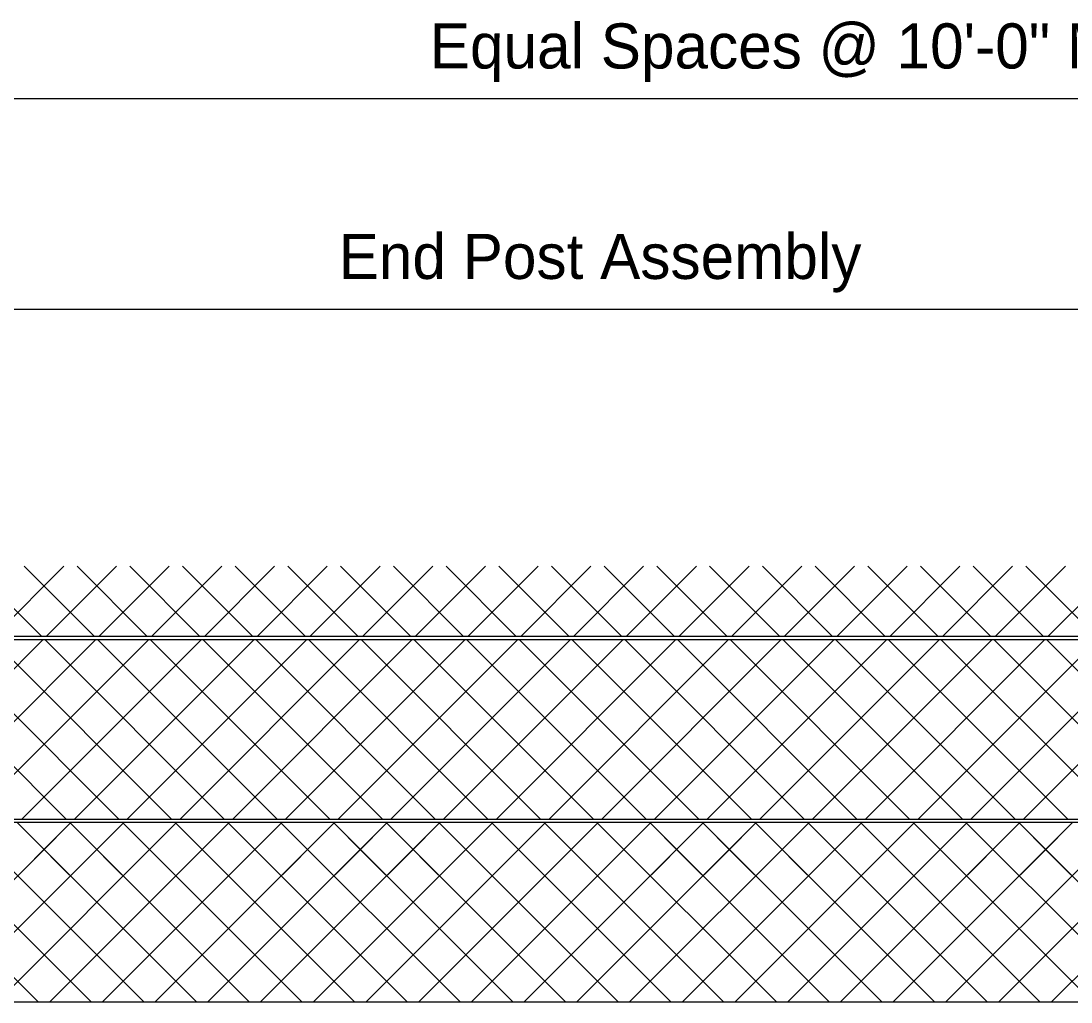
# Model space of a CAD drawing. Extents: x 0 to 41, y -96 to 25.
# Drawn here: x 7.464 to 12.158, y 20.57 to 24.956 of the extents above; entities that cross this region are included whole.
import ezdxf

# ---------------------------------------------------------------- set-up
doc = ezdxf.new("R2010")
doc.units = 0
for name, color, linetype in [('Dimension', 7, 'Continuous'), ('Miscellaneous', 7, 'Continuous'), ('SteelMisc', 7, 'Continuous'), ('TextStructures', 7, 'Continuous')]:
    doc.layers.add(name, color=color, linetype=linetype)

msp = doc.modelspace()

# ---------------------------------------------------------------- linework, layer by layer
at = {"layer": 'Dimension'}
for p, q in [((0.9439, 24.6092), (14.3237, 24.6092)), ((5.3237, 23.6682), (15.3237, 23.6682))]:
    msp.add_line(p, q, dxfattribs=at)
at = {"layer": 'Miscellaneous'}
for p, q in [((7.2428, 22.5181), (7.5553, 22.2055)), ((7.3422, 22.2055), (7.6547, 22.5181)), ((7.4785, 22.5181), (7.791, 22.2055)), ((7.5779, 22.2055), (7.8904, 22.5181)), ((7.7142, 22.5181), (8.0267, 22.2055)), ((7.8136, 22.2055), (8.1261, 22.5181)), ((7.9499, 22.5181), (8.2624, 22.2055)), ((8.0493, 22.2055), (8.3618, 22.5181)), ((8.1856, 22.5181), (8.4981, 22.2055)), ((8.285, 22.2055), (8.5975, 22.5181)), ((8.4213, 22.5181), (8.7338, 22.2055)), ((8.5207, 22.2055), (8.8332, 22.5181)), ((8.657, 22.5181), (8.9695, 22.2055)), ((8.7564, 22.2055), (9.0689, 22.5181)), ((8.8927, 22.5181), (9.2052, 22.2055)), ((8.9921, 22.2055), (9.3047, 22.5181)), ((9.1284, 22.5181), (9.4409, 22.2055)), ((9.2278, 22.2055), (9.5404, 22.5181)), ((9.3641, 22.5181), (9.6766, 22.2055)), ((9.4635, 22.2055), (9.7761, 22.5181)), ((9.5998, 22.5181), (9.9123, 22.2055)), ((9.6992, 22.2055), (10.0118, 22.5181)), ((9.8355, 22.5181), (10.148, 22.2055)), ((9.9349, 22.2055), (10.2475, 22.5181)), ((10.0712, 22.5181), (10.3837, 22.2055)), ((10.1706, 22.2055), (10.4832, 22.5181)), ((10.3069, 22.5181), (10.6194, 22.2055)), ((10.4063, 22.2055), (10.7189, 22.5181)), ((10.5426, 22.5181), (10.8551, 22.2055)), ((10.642, 22.2055), (10.9546, 22.5181)), ((10.7783, 22.5181), (11.0908, 22.2055)), ((10.8777, 22.2055), (11.1903, 22.5181)), ((11.014, 22.5181), (11.3265, 22.2055)), ((11.1134, 22.2055), (11.426, 22.5181)), ((11.2497, 22.5181), (11.5622, 22.2055)), ((11.3491, 22.2055), (11.6617, 22.5181)), ((11.4854, 22.5181), (11.7979, 22.2055)), ((11.5848, 22.2055), (11.8974, 22.5181)), ((11.7211, 22.5181), (12.0336, 22.2055)), ((11.8205, 22.2055), (12.1331, 22.5181)), ((11.9568, 22.5181), (12.2693, 22.2055)), ((12.0562, 22.2055), (12.3688, 22.5181)), ((6.7605, 21.3881), (7.5632, 22.1908)), ((6.8629, 22.1908), (7.6656, 21.3881)), ((6.9962, 21.3881), (7.7989, 22.1908)), ((7.0986, 22.1908), (7.9013, 21.3881)), ((7.2319, 21.3881), (8.0346, 22.1908)), ((7.3343, 22.1908), (8.137, 21.3881)), ((7.4676, 21.3881), (8.2703, 22.1908)), ((7.57, 22.1908), (8.3727, 21.3881)), ((7.7033, 21.3881), (8.506, 22.1908)), ((7.8058, 22.1908), (8.6084, 21.3881)), ((7.939, 21.3881), (8.7417, 22.1908)), ((8.0415, 22.1908), (8.8441, 21.3881)), ((8.1747, 21.3881), (8.9774, 22.1908)), ((8.2772, 22.1908), (9.0798, 21.3881)), ((8.4104, 21.3881), (9.2131, 22.1908)), ((8.5129, 22.1908), (9.3155, 21.3881)), ((8.6461, 21.3881), (9.4488, 22.1908)), ((8.7486, 22.1908), (9.5512, 21.3881)), ((8.8818, 21.3881), (9.6845, 22.1908)), ((8.9843, 22.1908), (9.7869, 21.3881)), ((9.1175, 21.3881), (9.9202, 22.1908)), ((9.22, 22.1908), (10.0226, 21.3881)), ((9.3532, 21.3881), (10.1559, 22.1908)), ((9.4557, 22.1908), (10.2583, 21.3881)), ((9.5889, 21.3881), (10.3916, 22.1908)), ((9.6914, 22.1908), (10.494, 21.3881)), ((9.8246, 21.3881), (10.6273, 22.1908)), ((9.9271, 22.1908), (10.7297, 21.3881)), ((10.0603, 21.3881), (10.863, 22.1908)), ((10.1628, 22.1908), (10.9654, 21.3881)), ((10.296, 21.3881), (11.0987, 22.1908)), ((10.3985, 22.1908), (11.2011, 21.3881)), ((10.5317, 21.3881), (11.3344, 22.1908)), ((10.6342, 22.1908), (11.4368, 21.3881)), ((10.7674, 21.3881), (11.5701, 22.1908)), ((10.8699, 22.1908), (11.6725, 21.3881)), ((11.0031, 21.3881), (11.8058, 22.1908)), ((11.1056, 22.1908), (11.9082, 21.3881)), ((11.2388, 21.3881), (12.0415, 22.1908)), ((11.3413, 22.1908), (12.1439, 21.3881)), ((11.4745, 21.3881), (12.2772, 22.1908)), ((11.577, 22.1908), (12.3796, 21.3881)), ((11.7103, 21.3881), (12.5129, 22.1908)), ((11.8127, 22.1908), (12.6153, 21.3881)), ((11.946, 21.3881), (12.7486, 22.1908)), ((12.0484, 22.1908), (12.851, 21.3881)), ((6.7375, 21.3734), (7.541, 20.57)), ((6.8851, 20.57), (7.6886, 21.3734)), ((6.9732, 21.3734), (7.7767, 20.57)), ((7.1208, 20.57), (7.9243, 21.3734)), ((7.2089, 21.3734), (8.0124, 20.57)), ((7.3565, 20.57), (8.16, 21.3734)), ((7.4446, 21.3734), (8.2481, 20.57)), ((7.5922, 20.57), (8.3957, 21.3734)), ((7.6803, 21.3734), (8.4838, 20.57)), ((7.8279, 20.57), (8.6314, 21.3734)), ((7.916, 21.3734), (8.7195, 20.57)), ((8.0636, 20.57), (8.8671, 21.3734)), ((8.1517, 21.3734), (8.9552, 20.57)), ((8.2993, 20.57), (9.1028, 21.3734)), ((8.3874, 21.3734), (9.1909, 20.57)), ((8.535, 20.57), (9.3385, 21.3734)), ((8.6231, 21.3734), (9.4266, 20.57)), ((8.7707, 20.57), (9.5742, 21.3734)), ((8.8589, 21.3734), (9.6623, 20.57)), ((9.0064, 20.57), (9.8099, 21.3734)), ((9.0946, 21.3734), (9.898, 20.57)), ((9.2422, 20.57), (10.0456, 21.3734)), ((9.3303, 21.3734), (10.1337, 20.57)), ((9.4779, 20.57), (10.2813, 21.3734)), ((9.566, 21.3734), (10.3694, 20.57)), ((9.7136, 20.57), (10.517, 21.3734)), ((9.8017, 21.3734), (10.6051, 20.57)), ((9.9493, 20.57), (10.7527, 21.3734)), ((10.0374, 21.3734), (10.8408, 20.57)), ((10.185, 20.57), (10.9884, 21.3734)), ((10.2731, 21.3734), (11.0765, 20.57)), ((10.4207, 20.57), (11.2241, 21.3734)), ((10.5088, 21.3734), (11.3122, 20.57)), ((10.6564, 20.57), (11.4598, 21.3734)), ((10.7445, 21.3734), (11.5479, 20.57)), ((10.8921, 20.57), (11.6955, 21.3734)), ((10.9802, 21.3734), (11.7836, 20.57)), ((11.1278, 20.57), (11.9312, 21.3734)), ((11.2159, 21.3734), (12.0193, 20.57)), ((11.3635, 20.57), (12.1669, 21.3734)), ((11.4516, 21.3734), (12.255, 20.57)), ((11.5992, 20.57), (12.4026, 21.3734)), ((11.6873, 21.3734), (12.4907, 20.57)), ((11.8349, 20.57), (12.6383, 21.3734)), ((11.923, 21.3734), (12.7264, 20.57)), ((12.0706, 20.57), (12.874, 21.3734)), ((7.4537, 21.1385), (7.6203, 21.3051)), ((7.5129, 21.3051), (7.6795, 21.1385)), ((7.6894, 21.1385), (7.856, 21.3051)), ((7.7486, 21.3051), (7.9152, 21.1385)), ((7.9251, 21.1385), (8.0917, 21.3051)), ((7.9843, 21.3051), (8.1509, 21.1385)), ((8.1608, 21.1385), (8.3274, 21.3051)), ((8.22, 21.3051), (8.3867, 21.1385)), ((8.3965, 21.1385), (8.5631, 21.3051)), ((8.4557, 21.3051), (8.6224, 21.1385)), ((8.6322, 21.1385), (8.7988, 21.3051)), ((8.6914, 21.3051), (8.8581, 21.1385)), ((8.8679, 21.1385), (9.0345, 21.3051)), ((8.9271, 21.3051), (9.0938, 21.1385)), ((9.1036, 21.1385), (9.2702, 21.3051)), ((9.1628, 21.3051), (9.3295, 21.1385)), ((9.3393, 21.1385), (9.5059, 21.3051)), ((9.3985, 21.3051), (9.5652, 21.1385)), ((9.575, 21.1385), (9.7416, 21.3051)), ((9.6342, 21.3051), (9.8009, 21.1385)), ((9.8107, 21.1385), (9.9773, 21.3051)), ((9.8699, 21.3051), (10.0366, 21.1385)), ((10.0464, 21.1385), (10.213, 21.3051)), ((10.1056, 21.3051), (10.2723, 21.1385)), ((10.2821, 21.1385), (10.4487, 21.3051)), ((10.3413, 21.3051), (10.508, 21.1385)), ((10.5178, 21.1385), (10.6845, 21.3051)), ((10.577, 21.3051), (10.7437, 21.1385)), ((10.7535, 21.1385), (10.9202, 21.3051)), ((10.8127, 21.3051), (10.9794, 21.1385)), ((10.9892, 21.1385), (11.1559, 21.3051)), ((11.0484, 21.3051), (11.2151, 21.1385)), ((11.2249, 21.1385), (11.3916, 21.3051)), ((11.2841, 21.3051), (11.4508, 21.1385)), ((11.4606, 21.1385), (11.6273, 21.3051)), ((11.5198, 21.3051), (11.6865, 21.1385)), ((11.6963, 21.1385), (11.863, 21.3051)), ((11.7555, 21.3051), (11.9222, 21.1385)), ((11.932, 21.1385), (12.0987, 21.3051)), ((11.9912, 21.3051), (12.1579, 21.1385))]:
    msp.add_line(p, q, dxfattribs=at)
at = {"layer": 'SteelMisc'}
for p, q in [((5.6284, 22.2055), (15.0028, 22.2055)), ((5.6317, 22.1908), (15.0294, 22.1908)), ((5.6284, 21.3881), (15.0028, 21.3881)), ((5.6317, 21.3734), (15.0294, 21.3734)), ((5.6284, 20.57), (15.0028, 20.57))]:
    msp.add_line(p, q, dxfattribs=at)

# ---------------------------------------------------------------- texts
at = {"layer": 'TextStructures'}
for s, p in [('Equal Spaces @ 10\'-0" Max. (Posts may be shifted minimally to meet required clearances)', (9.2913, 24.7438)), ('End Post Assembly', (8.8839, 23.8028))]:
    msp.add_text(s, height=0.2016, dxfattribs=at).set_placement(p)

doc.saveas('drawing.dxf')
